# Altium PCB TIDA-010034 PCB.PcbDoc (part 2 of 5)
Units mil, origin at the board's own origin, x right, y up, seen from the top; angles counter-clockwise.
Board outline 4497.63 x 4881.81 mil, 4 copper layers (Top Layer, Signal Layer 1, Signal Layer 2, Bottom Layer), stack 62.18 mil thick; 483 components, 240 nets, 1255 pads, 589 vias.
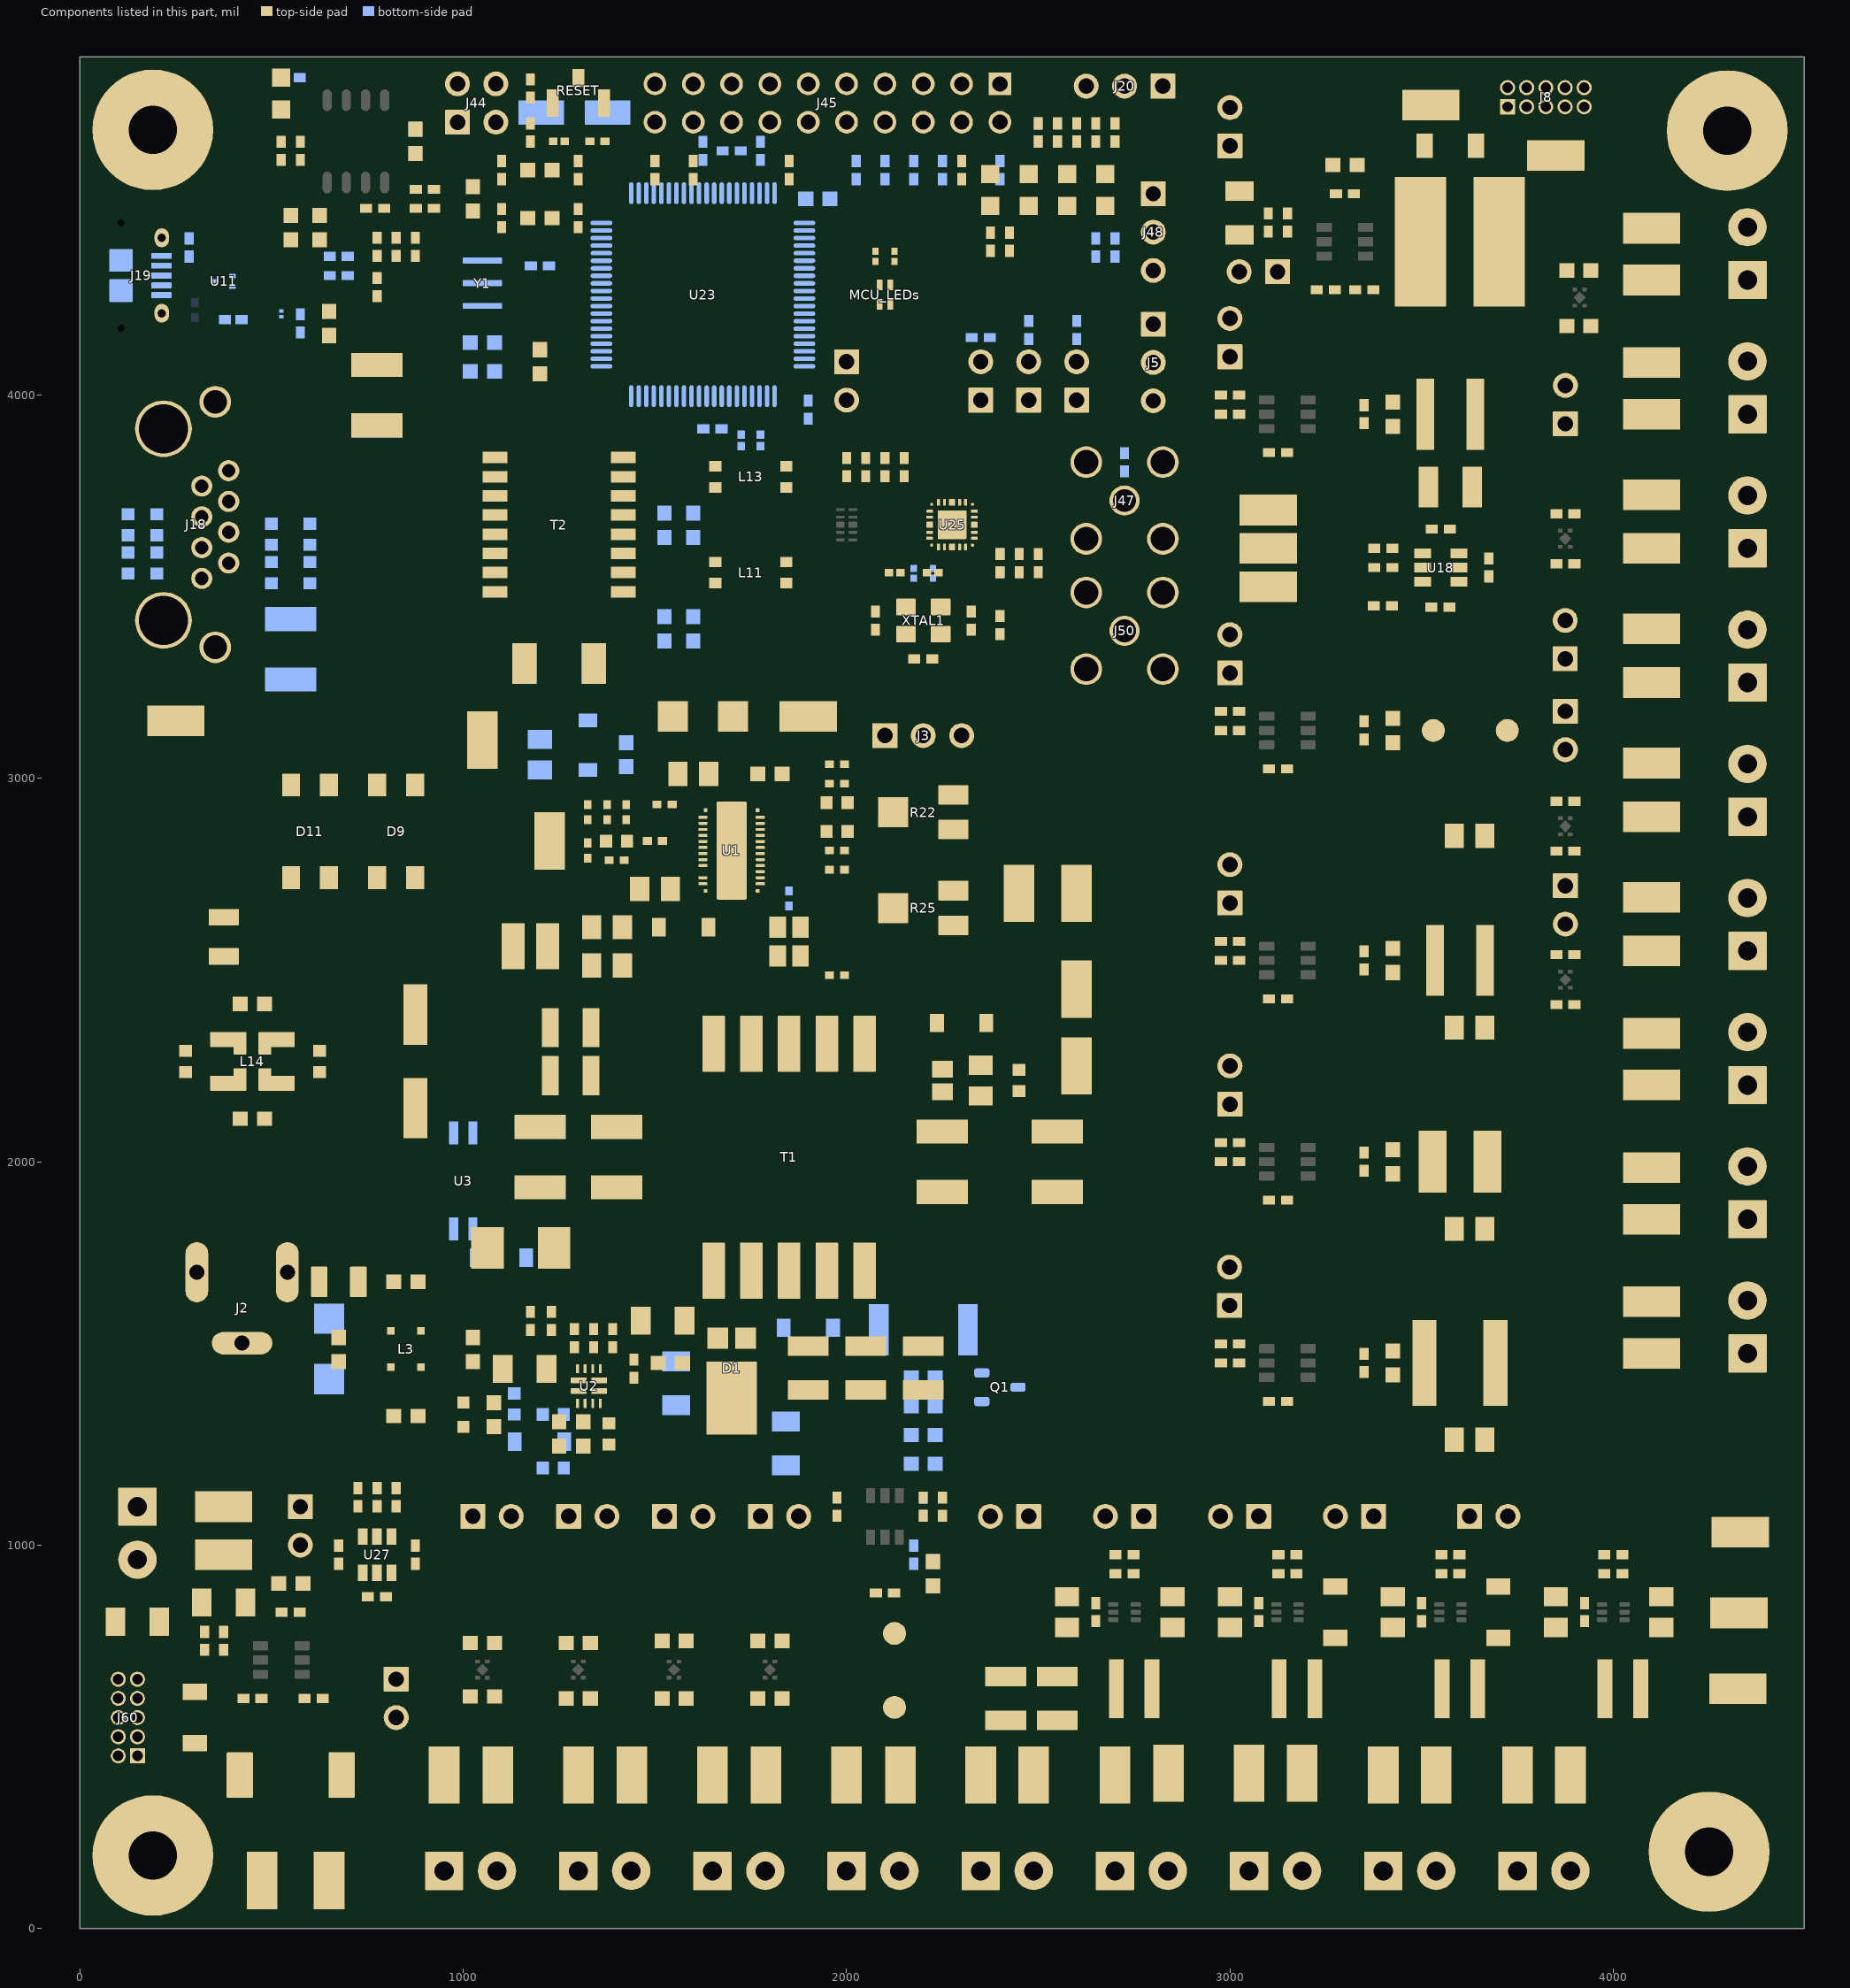
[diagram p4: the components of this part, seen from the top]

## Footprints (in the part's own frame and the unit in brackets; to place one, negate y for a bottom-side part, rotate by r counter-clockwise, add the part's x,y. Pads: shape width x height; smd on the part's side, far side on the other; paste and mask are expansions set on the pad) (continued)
DRT0003A [mm] "SOTFL, 3-Leads, Body 1x1mm (inc leads), Pitch 0.35mm"
  rect 0.3x0.45 smd: 1(-0.35,-0.575) 2(0.35,-0.575) 3(0,0.575)
  silkscreen extent -0.85,-0.63 0.67,0.58, body extent -0.52,-0.42 0.52,0.42, height 0.5
ECS_ECS-33Q [mm] "SMD, 4-Leads, Body 2.5x3.2mm"
  rrect9% 1.1x1.3 smd: 1(-0.9,1.15) 2(-0.9,-1.15) 3(0.9,-1.15) 4(0.9,1.15)
  silkscreen extent -1.75,0.6 -1.75,1.7, body extent -1.3,-1.65 1.3,1.65, height 0.81
FCC_disclaimer [mil]
FCI_10118194-0001LF [mm] "USB-micro B USB 2.0, 0.65mm, 5 Pos, R/A, SMT"
  rrect25% 0.4x1.35 smd: 1(-1.3,4.125) 2(-0.65,4.125) 3(0,4.125) 4(0.65,4.125) 5(1.3,4.125)
  rrect100% 1.25x0.95 hole 0.55 slot 0.85 at 0 deg: 6(-2.5,4.15) 7(2.5,4.15)
  round 0 hole 0.5 slot 1.15 at 90 deg: 8(-3.5,1.45) 9(3.5,1.45)
  rrect7% 1.5x1.55 smd: 10(-1,1.45) 11(1,1.45)
  Top Layer region: -3.445,0.675 -3.636,0.713 -3.799,0.821 -3.907,0.984 -3.945,1.175 -3.945,1.175 -3.945,1.175 -3.945,1.725 -3.907,1.916 -3.799,2.079 -3.636,2.187 -3.445,2.225 -3.445,2.225 -2.3,2.225 -2.3,0.675
  Top Layer region: 3.445,0.675 3.636,0.713 3.799,0.821 3.907,0.984 3.945,1.175 3.945,1.175 3.945,1.175 3.945,1.725 3.907,1.916 3.799,2.079 3.636,2.187 3.445,2.225 3.445,2.225 2.3,2.225 2.3,0.675
  silkscreen extent -4,2.6 3.7,4.3, body extent -4.02,-1.23 4.03,4.35, height 2.73
Fuse_USF1206 [mm] "SMD, 2-Leads, Body 3.2x1.6mm"
  rrect9% 1.1x2 smd: 1(-1.3,0) 2(1.3,0)
  body extent -1.6,-0.8 1.6,0.8, height 0.65
HSMF-C165_RG [mm] "SMD, 4-Leads, Body 1.6x0.8mm"
  rect 0.7x0.4 smd: 1(-0.65,0.35) 2(-0.65,-0.35) 3(0.65,0.35) 4(0.65,-0.35)
  silkscreen extent -1,-0.8 1.5,0.8, body extent -0.85,-0.45 0.85,0.45, height 0.51
IND_1255AY [mm] "Toko DG6045C 1255AY"
  rect 1.6x5.7 smd: 1(-2.35,0) 2(2.35,0)
  silkscreen extent -1.25,-2.8 1.25,2.8, body extent -3.15,-3.15 3.15,3.15, height 4.5
Keystone_1902C [mil] "Hex Standoff, 4-40 threaded, nylon"
  body extent -145,-126 146,126, height 501
Keystone_5019 [mm] "Test Point, Miniature, SMT"
  rect 3.8x2.03 smd: 1(0,0)
  silkscreen extent -2.31,-1.42 2.31,1.42, body extent -1.9,-1.02 1.9,1.02, height 2.29
Linkcom_LDT0937-50 [mm] "SMD, 10-Leads, Body 14x15.1mm, Pitch 2.5mm"
  rrect7% 1.5x3.725 smd paste+0: 1(-5,7.512) 2(-2.5,7.512) 3(0,7.512) 4(2.5,7.512) 5(5,7.512) 6(5,-7.512) 7(2.5,-7.512) 8(0,-7.512) 9(-2.5,-7.512) 10(-5,-7.512)
  silkscreen extent -7.4,-7.55 7,7.55, body extent -7,-8.75 7,8.75, height 14
LPS8045B [mm] "COILCRAFT"
  rect 3.4x8.61 smd: 1(-2.605,0) 2(2.605,0)
  silkscreen extent -0.6,-4.15 0.6,4.15, body extent -4.04,-4.04 4.04,4.04, height 4.7
LQH5BPN_38 [mm] "MURATA"
  rect 1.85x4.1 smd: 1(-1.825,0) 2(1.825,0)
  silkscreen extent -2.5,-2.65 2.5,2.65, body extent -2.55,-2.55 2.55,2.55, height 4
ME3220 [mm] "Coilcraft SMT Power Inductor ME3220 inductors"
  rect 1.52x3.05 smd: 1(-1.145,0) 2(1.145,0)
  silkscreen extent -2.38,-1.88 2.34,1.88, body extent -1.75,-1.41 1.75,1.4
MF06A_N [mm] "SOT23, 6-Leads, Body 2.9x1.6mm, Pitch 0.95mm, Lead Span 2.8mm, IPC Medium Density"
  rect 1.1x0.65 smd: 1(-1.2,0.95) 2(-1.2,0) 3(-1.2,-0.95) 4(1.2,-0.95) 5(1.2,0) 6(1.2,0.95)
  silkscreen extent -1.33,-1.55 0.25,1.95, body extent -0.9,-1.55 0.9,1.55, height 1.22
MFP04A [mm] "FAIRCHILD optocoupler"
  rect 1.52x0.61 smd: 1(-3.175,0.635) 2(-3.175,-0.635) 3(3.175,-0.635) 4(3.175,0.635)
  silkscreen extent -2.28,-1.4 2.2,1.8, body extent -3.6,-1.34 3.6,1.34, height 2.39
MiniDIP [mm] "Land pattern created based on STEP model."
  rect 1.52x1.2 smd: 1(-3.075,1.25) 2(-3.075,-1.25) 3(3.075,-1.25) 4(3.075,1.25)
  silkscreen extent -4.19,-2.54 4.19,2.54, body extent -3.5,-2.45 3.5,2.45, height 2.75
Murata_CSTCR_G15L [mm] "Murata"
  rrect25% 0.4x2.6 smd: 1(-1.5,0) 2(0,0) 3(1.5,0)
  body extent -2.3,-1.05 2.3,1.05, height 1.2
MuRata_DLW44SN [mm] "SMD, 4-Leads, Body 4.2x4.2mm"
  rrect12% 1.5x0.85 smd: 1(-1.2,0.825) 2(-1.2,-0.825) 3(1.2,-0.825) 4(1.2,0.825)
  rrect10% 1x2.4 smd: ""(-1.45,1.6) ""(-1.45,-1.6) ""(1.45,1.6) ""(1.45,-1.6)
  silkscreen extent -0.7,-2.2 0.6,2.5, body extent -2.1,-2.1 2.1,2.1, height 1.5
"NY PMS 440 0025 PH" [mm] "4-40 nylon screw and mounting hole"
  round 8 hole 3.2: 1(0,0)
  body extent -3.3,-3.3 3.3,3.3, height 2.69
Pb-Free_Overlay_Small [mil]
  silkscreen extent -46,-46 46,46
PN0080A_N [mm] "QFP, 80-Leads, Body 12x12mm, Pitch 0.5mm, IPC Medium Density"
  oval 1.45x0.3 smd: 1(-6.725,4.75) 2(-6.725,4.25) 3(-6.725,3.75) 4(-6.725,3.25) 5(-6.725,2.75) 6(-6.725,2.25) 7(-6.725,1.75) 8(-6.725,1.25) 9(-6.725,0.75) 10(-6.725,0.25) 11(-6.725,-0.25) 12(-6.725,-0.75) 13(-6.725,-1.25) 14(-6.725,-1.75) 15(-6.725,-2.25) 16(-6.725,-2.75) 17(-6.725,-3.25) 18(-6.725,-3.75) 19(-6.725,-4.25) 20(-6.725,-4.75) 41(6.725,-4.75) 42(6.725,-4.25) 43(6.725,-3.75) 44(6.725,-3.25) 45(6.725,-2.75) 46(6.725,-2.25) 47(6.725,-1.75) 48(6.725,-1.25) 49(6.725,-0.75) 50(6.725,-0.25) 51(6.725,0.25) 52(6.725,0.75) 53(6.725,1.25) 54(6.725,1.75) 55(6.725,2.25) 56(6.725,2.75) 57(6.725,3.25) 58(6.725,3.75) 59(6.725,4.25) 60(6.725,4.75)
  oval 0.3x1.45 smd: 21(-4.75,-6.725) 22(-4.25,-6.725) 23(-3.75,-6.725) 24(-3.25,-6.725) 25(-2.75,-6.725) 26(-2.25,-6.725) 27(-1.75,-6.725) 28(-1.25,-6.725) 29(-0.75,-6.725) 30(-0.25,-6.725) 31(0.25,-6.725) 32(0.75,-6.725) 33(1.25,-6.725) 34(1.75,-6.725) 35(2.25,-6.725) 36(2.75,-6.725) 37(3.25,-6.725) 38(3.75,-6.725) 39(4.25,-6.725) 40(4.75,-6.725) 61(4.75,6.725) 62(4.25,6.725) 63(3.75,6.725) 64(3.25,6.725) 65(2.75,6.725) 66(2.25,6.725) 67(1.75,6.725) 68(1.25,6.725) 69(0.75,6.725) 70(0.25,6.725) 71(-0.25,6.725) 72(-0.75,6.725) 73(-1.25,6.725) 74(-1.75,6.725) 75(-2.25,6.725) 76(-2.75,6.725) 77(-3.25,6.725) 78(-3.75,6.725) 79(-4.25,6.725) 80(-4.75,6.725)
  silkscreen extent -6.85,-5.6 5.6,5.6, body extent -7,-7 7,7, height 1.56
PowerDI5 [mm] "Diodes Inc recommended land pattern, ap02001.pdf rev 60"
  rect 1.4x1.39 smd: 1(-1.991,0.92) 2(-1.991,-0.92)
  rect 4.86x3.36 smd: 3(1.991,0)
  silkscreen extent -1.7,-2.1 3.8,2.1, body extent -2.27,-2.03 4.33,2.03, height 1.17
PULSE_H2019FNL [mil] "PULSE"
  rect 65x30 smd paste+0: 1(-167.51,174.99) 2(-167.51,124.99) 3(-167.51,74.99) 4(-167.51,24.99) 5(-167.51,-25.01) 6(-167.51,-75.01) 7(-167.51,-125.01) 8(-167.51,-175.01) 9(167.49,-175.01) 10(167.49,-125.01) 11(167.49,-75.01) 12(167.49,-25.01) 13(167.49,24.99) 14(167.49,74.99) 15(167.49,124.99) 16(167.49,174.99)
  silkscreen extent -208,-250 179,250, body extent -179,-250 179,250, height 236
QTLP630C_Green [mm] "SMT, 2-Leads, Body 2x1.25mm"
  rect 1.2x1.2 smd: 1(-1.05,0) 2(1.05,0)
  silkscreen extent -0.15,-0.8 2.15,0.8, body extent -1.1,-0.73 1.1,0.73, height 1.22
RJJ0023B [mm] "SMD, 23-Leads, Body 4x6mm"
  rrect50% 0.6x0.2 smd: 1(-1.9,2.2) 2(-1.9,1.8) 3(-1.9,1.4) 4(-1.9,1) 5(-1.9,0.6) 6(-1.9,0.2) 7(-1.9,-0.2) 8(-1.9,-0.6) 9(-1.9,-1) 10(-1.9,-1.4) 11(-1.9,-1.8) 12(-1.9,-2.2) 13(1.9,-2.2) 14(1.9,-1.8) 15(1.9,-1.4) 16(1.9,-1) 17(1.9,-0.6) 18(1.9,-0.2) 19(1.9,0.2) 20(1.9,0.6) 21(1.9,1) 23(1.9,1.8) 24(1.9,2.2)
  rrect10% 2x6.5 smd paste-2 mask-2: 25(0,0)
  rrect40% 0.25x0.25 smd: A1(-1.725,2.675) A2(-1.725,-2.675) A3(1.725,-2.675) A4(1.725,2.675)
  rrect50% 0.2x0.46 on Top Paste: ""(-0.8,2.97) ""(-0.8,-2.97) ""(-0.4,2.97) ""(-0.4,-2.97) ""(0,2.97) ""(0,-2.97) ""(0.4,2.97) ""(0.4,-2.97) ""(0.8,2.97) ""(0.8,-2.97)
  rrect12% 0.85x1.12 on Top Paste: ""(-0.525,1.98) ""(-0.525,0.66) ""(-0.525,-0.66) ""(-0.525,-1.98) ""(0.525,1.98) ""(0.525,0.66) ""(0.525,-0.66) ""(0.525,-1.98)
  silkscreen extent -2.2,-3.2 2.2,3.2, body extent -2,-3 2,3, height 1
RLL0024A [mm] "QFN, 24-Leads, Body 3x3mm"
  rrect50% 0.45x0.2 smd: 1(-1.475,0.9) 2(-1.475,0.5) 4(-1.475,-0.5) 5(-1.475,-0.9) 13(1.475,-0.9) 14(1.475,-0.5) 16(1.475,0.5) 17(1.475,0.9)
  rrect25% 0.45x0.4 smd: 3(-1.475,0) 15(1.475,0)
  rrect50% 0.2x0.2 smd: 6(-1.35,-1.35) 12(1.35,-1.35) 18(1.35,1.35) 24(-1.35,1.35)
  rrect50% 0.2x0.45 smd: 7(-0.9,-1.475) 8(-0.5,-1.475) 10(0.5,-1.475) 11(0.9,-1.475) 19(0.9,1.475) 20(0.5,1.475) 22(-0.5,1.475) 23(-0.9,1.475)
  rrect25% 0.4x0.45 smd: 9(0,-1.475) 21(0,1.475)
  rrect5% 1.9x1.9 smd paste-1.9: 25(0,0)
  rrect6% 1.71x1.71 on Top Paste: ""(0,0)
  silkscreen extent -1.78,-1.78 1.78,1.78, body extent -1.58,-1.58 1.58,1.58, height 1.01
RUX0012A [mm] "VQFN-HR-12"
  rrect25% 1.05x0.4 smd: 1(-0.675,0.325) 2(-0.675,-0.375) 7(0.675,-0.375) 8(0.675,0.325)
  rrect40% 0.2x0.6 smd: 3(-0.75,-1.15) 4(-0.25,-1.15) 5(0.25,-1.15) 6(0.75,-1.15) 9(0.75,1.15) 10(0.25,1.15) 11(-0.25,1.15) 12(-0.75,1.15)
  silkscreen extent -1.15,-1.4 1.15,1.35, body extent -1.05,-1.3 1.05,1.3, height 1
Samtec_HTSW-102-07-G-S [mm] "Samtec 100mil, 1x2, 230 mil above insulator"
  rrect6% 1.65x1.65 hole 1.016: 1(-1.27,0)
  round 1.65 hole 1.016: 2(1.27,0)
  silkscreen extent -3.3,-1.27 2.54,1.27, body extent -2.54,-1.27 2.54,1.27, height 8.38
Samtec_HTSW-103-07-G-S [mm] "Samtec 100mil, 1x3, 230 mil above insulator"
  rrect6% 1.65x1.65 hole 1.016: 1(-2.54,0)
  round 1.65 hole 1.016: 2(0,0) 3(2.54,0)
  silkscreen extent -4.57,-1.27 3.81,1.27, body extent -3.81,-1.27 3.81,1.27, height 8.38
SM_RADIAL_E [mm] "8 x 6.2mm:  Panasonic E"
  rect 4x1.6 smd: 1(-3.1,0) 2(3.1,0)
  silkscreen extent -4.25,-4.25 4.25,4.25, body extent -4.25,-4.25 4.25,4.25, height 6.5
SMA [mm] "Molded Diode, 2-Leads, Body 4.3x2.6mm, IPC Medium Density, based on OnSemi component dimensions and land pattern"
  rect 2x2 smd: 1(-2,0) 2(2,0)
  silkscreen extent -3.66,-1.57 2.79,1.57, body extent -2.6,-1.3 2.6,1.3, height 2.42
SMB [mil] "Molded Diode, 2-Leads, Body 5.4x3.6mm, IPC Medium Density, based on OnSemi component dimensions"
  rect 85x107.99 smd: 1(-87.01,0) 2(87.01,0)
  silkscreen extent -155,-82 125,82, body extent -106,-71 106,71, height 91
SOD-123 [mm] "On Semi recommended land pattern"
  rect 0.915x1.22 smd: 1(-1.637,0) 2(1.637,0)
  silkscreen extent -2.74,-1.17 2.03,1.17, body extent -1.93,-0.9 1.93,0.9, height 1.35
SOD-523 [mm] "NXP Semiconductor recommended land pattern, nominal STEP model"
  rect 0.8x0.6 smd paste-0.05: 1(-0.55,0) 2(0.55,0)
  silkscreen extent -1.65,-0.66 1.2,0.66, body extent -0.8,-0.4 0.8,0.4, height 0.72
SOT-23 [mm] "SOT23, 3-Leads, Body 2.9x1.3mm, Pitch 0.95mm, Lead Span 2.5mm, IPC Medium Density"
  rrect50% 1x0.6 smd: 1(-1.2,0.95) 2(-1.2,-0.95) 3(1.2,0)
  silkscreen extent -1.63,-1.5 0.7,1.5, body extent -1.16,-1.45 1.21,1.45, height 1
SRT8045 [mil] "SMD, 2-Leads, Body 8x8.4mm"
  round 60 smd: 1(-94.49,0) 2(98.43,0)
  Top Layer region: 157.48,-102.36 102.36,-157.48 35.43,-157.48 35.43,157.48 157.48,157.48
  Top Layer region: -157.48,-102.36 -102.36,-157.48 -35.43,-157.48 -35.43,157.48 -157.48,157.48
  silkscreen extent -169,-177 169,177, body extent -163,-171 163,171, height 181
Sullins_xxxC010DAAN [mm] "Header, 2.54mm, 10x2, TH"
  rect 1.5x1.5 hole 1: 1(-1.27,11.43)
  round 1.5 hole 1: 2(1.27,11.43) 3(-1.27,8.89) 4(1.27,8.89) 5(-1.27,6.35) 6(1.27,6.35) 7(-1.27,3.81) 8(1.27,3.81) 9(-1.27,1.27) 10(1.27,1.27) 11(-1.27,-1.27) 12(1.27,-1.27) 13(-1.27,-3.81) 14(1.27,-3.81) 15(-1.27,-6.35) 16(1.27,-6.35) 17(-1.27,-8.89) 18(1.27,-8.89) 19(-1.27,-11.43) 20(1.27,-11.43)
  silkscreen extent -2.5,-12.7 2.5,13.14, body extent -2.5,-12.7 2.5,12.7, height 8.34
SW_B3U-1100P [mm] "SMD, 3-Leads, Body 3x2.5mm"
  rect 0.8x1.8 smd: 1(-1.7,0) 2(1.7,0)
  rect 0.8x1.2 smd: 3(0,1.65)
  silkscreen extent -1.83,-1.25 1.5,1.77, body extent -2,-1.25 2,1.9, height 1.6
TDK_ACT45L [mm] "SMD, 4-Leads, Body 4.5x3.2mm"
  rect 0.8x0.7 smd: 1(-2.35,0.7) 2(-2.35,-0.7) 3(2.35,-0.7) 4(2.35,0.7)
  silkscreen extent -2.35,-1.7 2.25,2, body extent -2.25,-1.7 2.25,1.7, height 2.95
TE_5-1814832-1 [mm] "SMA Straight PCB Socket Die Cast, TH"
  round 2 hole 1.5: 1(0,0)
  round 2.1 hole 1.6: 2(-2.54,2.54) 3(-2.54,-2.54) 4(2.54,-2.54) 5(2.54,2.54)
  silkscreen extent -3.2,-3.2 3.2,3.2, body extent -3.2,-3.2 3.2,3.2, height 9.5
TEC_1-406541-1 [mm] "TE Connectivity"
  round 1.4 hole 0.89: 1(3.56,-0.18) 2(2.54,1.6) 3(1.52,-0.18) 4(0.5,1.6) 5(-0.52,-0.18) 6(-1.54,1.6) 7(-2.56,-0.18) 8(-3.58,1.6)
  round 2.1 hole 1.57: 9(8.12,0.71) 10(-8.14,0.71)
  round 3.759 hole 3.251: 11(6.34,-2.72) 12(-6.36,-2.72)
  silkscreen extent -9.69,-8 9.69,8.06, body extent -9.33,-8 9.31,7.75, height 14.8
TERM_BLK_ED555-2DS [mil]
  rrect4% 100x100 hole 50: 1(0,0)
  round 100 hole 50: 2(138,0)
  silkscreen extent -96,-159 215,113, body extent -69,-150 207,106, height 323
TSW-102-07-G-D [mm] "Samtec 100mil, 2x2, 230 mil above insulator"
  rrect6% 1.65x1.65 hole 1.016: 1(-1.27,-1.27)
  round 1.65 hole 1.016: 2(-1.27,1.27) 3(1.27,-1.27) 4(1.27,1.27)
  silkscreen extent -2.77,-3.09 2.54,2.54, body extent -2.54,-2.54 2.54,2.54, height 8.38
TSW-102-07-G-S [mm] "Samtec 100mil, 1x2, 230 mil above insulator"
  rrect6% 1.65x1.65 hole 1.016: 1(-1.27,0)
  round 1.65 hole 1.016: 2(1.27,0)
  silkscreen extent -2.54,-1.27 2.54,1.65, body extent -2.54,-1.27 2.54,1.27, height 8.38
TSW-103-07-X-S [mm] "Samtec Header, 100mil, 1x3"
  rect 1.65x1.65 hole 1.016: 1(-2.54,0)
  round 1.65 hole 1.016: 2(0,0) 3(2.54,0)
  silkscreen extent -4.57,-1.52 4.06,1.52, body extent -3.81,-1.27 3.81,1.27, height 8.38
WL-SMCW_YELLOW [mm] "WURTH"
  rect 0.8x0.8 smd: 1(-0.8,0) 2(0.8,0)
  silkscreen extent -1.9,-0.8 1.2,0.8, body extent -0.85,-0.45 0.85,0.45, height 0.8
X3-DFN0603-2 [mm] "SMD, 2-Leads, Body 0.62x0.32mm"
  rect 0.23x0.3 smd mask+0.102: 1(-0.19,0) 2(0.19,0)
  silkscreen extent -0.69,-0.48 0.32,0.48, body extent -0.32,-0.17 0.32,0.17, height 0.35
XEL4030_310 [mm] "SMD, 2-Leads, Body 4x4mm, Pitch 2.37mm"
  rect 0.98x3.9 smd: 1(-1.185,0) 2(1.185,0)
  silkscreen extent -2.3,-2.3 2.3,2.3, body extent -2.15,-2.15 2.15,2.15, height 3.1
XFL5030 [mm] "SMD, 2-Leads, Body 5.48x5.28mm"
  rect 1.18x4.7 smd: 1(-1.655,0) 2(1.655,0)
  silkscreen extent -2.74,-2.84 2.74,2.84, body extent -2.74,-2.84 2.74,2.84, height 3.1

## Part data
1.1V 1.1V 1.5VA 1.5VA 1.8VA 1.8VA 1.8VD 1.8VD 1.35V 1.35V 2.8VA 2.8VA 3.3V 3.3VA 3.3VA 3.3VD 5V 5V 12V EARTH GND GND GND GND GND GND GND GND GND GND GND GND GND GND GND GND GND GND GND Loop PGND RSNS SEQ1_FLAG1 SEQ1_FLAG2 SEQ1_FLAG3 SEQ2_FLAG1 SEQ2_FLAG2 SEQ2_FLAG3 VBIAS VCC VLED1 VLED1_FB VLED2 VLED2_FB VPD VSS: library part 5019, "Test Point, Miniature, SMT", Manufacturer=Keystone, Supplier Part Number 1=36-5019TR-ND
+3.3V LED0_H LED0_L LED2_H LED2_L: library part CMP-0002917-1, "LED, Green, SMD", Color=Green, Manufacturer=Everlight, Supplier Part Number 1=1080-1411-1-ND, Value1=W, Value2=2.1V
+12V_PoE: "LED, Yellow, SMD", Color=yellow, Manufacturer="Wurth Elektronik", Supplier Part Number 1=732-4981-1-ND, Value1=W, Value2=2V
C1 C2 C27 C28: "CAP, CERM, 2200 pF, 2000 V, +/- 10%, X7R, 1812", Cap_Case=1812, Manufacturer=TDK, Supplier Part Number 1=445-2389-1-ND, TempCo=X7R, Tolerance_%=10, Value1=Unknown, Value2=2000V, ValueDisplayed=2200pF
C3 C14: "CAP, CERM, 0.1 µF, 100 V, +/- 10%, X7R, 0805", Cap_Case=0805, Manufacturer=TDK, Supplier Part Number 1=445-1418-1-ND, TempCo=X7R, Tolerance_%=10, Value1="0.020726 ohm", Value2=100V, ValueDisplayed=0.1µF
C4: "CAP, AL, 10 µF, 100 V, +/- 20%, AEC-Q200 Grade 3, SMD", Cap_Case=8.0x6.0mm, Manufacturer=Panasonic, Supplier Part Number 1=PCE3966CT-ND, Tolerance_%=20, Value1=Unknown, Value2=100V, ValueDisplayed=10µF
C5 C6: "CAP, CERM, 2.2 µF, 100 V, +/- 10%, X7R, 1210", Cap_Case=1210, Manufacturer=MuRata, Supplier Part Number 1=490-3385-1-ND, TempCo=X7R, Tolerance_%=10, Value1="0.007 ohm", Value2=100V, ValueDisplayed=2.2µF
C7 C8 C9: "CAP, CERM, 22 µF, 25 V,+/- 10%, X7R, 1210", Cap_Case=1210, Manufacturer=MuRata, Supplier Part Number 1=490-5313-1-ND, TempCo=X7R, Tolerance_%=10, Value1="0.002334 ohm", Value2=25V, ValueDisplayed=22µF
C10: "CAP, CERM, 680 pF, 100 V, +/- 10%, X7R, 0603", Cap_Case=0603, Manufacturer=AVX, Supplier Part Number 1=478-1198-1-ND, TempCo=X7R, Tolerance_%=10, Value1="0.332 ohm", Value2=100V, ValueDisplayed=680pF
C11 C16: "CAP, CERM, 1 µF, 50 V,+/- 10%, X7R, 0805", Cap_Case=0805, Manufacturer=MuRata, Supplier Part Number 1=490-4736-1-ND, TempCo=X7R, Tolerance_%=10, Value2=50V, ValueDisplayed=1µF
C12 C15 C26: "CAP, CERM, 0.1 µF, 50 V,+/- 10%, X7R, 0603", Cap_Case=0603, Manufacturer=AVX, Supplier Part Number 1=478-5052-1-ND, TempCo=X7R, Tolerance_%=10, Value2=50V, ValueDisplayed=0.1µF
C13: "CAP, CERM, 0.22 µF, 100 V,+/- 10%, X7R, 0805", Cap_Case=0805, Manufacturer=MuRata, Supplier Part Number 1=GRM21AR72A224KAC5-ND, TempCo=X7R, Tolerance_%=10, Value2=100V, ValueDisplayed=0.22µF
C17: "CAP, CERM, 100 pF, 50 V,+/- 5%, C0G/NP0, 0402", Cap_Case=0402, Manufacturer="Wurth Elektronik", Supplier Part Number 1=732-7475-1-ND, TempCo=C0G/NP0, Tolerance_%=5, Value2=50V, ValueDisplayed=100pF
C18: "CAP, CERM, 0.01 µF, 100 V,+/- 20%, X7R, 0603", Cap_Case=0603, Manufacturer=AVX, Supplier Part Number 1=478-3701-1-ND, TempCo=X7R, Tolerance_%=20, Value1="0.098 ohm", Value2=100V, ValueDisplayed=0.01µF
C19 C20 C54 C55: "CAP, CERM, 1000 pF, 100 V, +/- 10%, X7R, 0603", Cap_Case=0603, Manufacturer=MuRata, Supplier Part Number 1=490-1472-1-ND, TempCo=X7R, Tolerance_%=10, Value1=Unknown, Value2=100V, ValueDisplayed=1000pF
C22 C25: "CAP, CERM, 0.1 µF, 25 V, +/- 10%, X7R, 0603", Cap_Case=0603, Manufacturer=TDK, Supplier Part Number 1=445-1316-1-ND, TempCo=X7R, Tolerance_%=10, Value1=Unknown, Value2=25V, ValueDisplayed=0.1µF
C24: "CAP, CERM, 2200 pF, 50 V, +/- 10%, X7R, 0603", Cap_Case=0603, Manufacturer=MuRata, Supplier Part Number 1=490-1500-1-ND, TempCo=X7R, Tolerance_%=10, Value1=Unknown, Value2=50V, ValueDisplayed=2200pF
C29 C30 C38 C39 C46 C50 C76 C137: "CAP, CERM, 0.1 µF, 10 V,+/- 10%, X7R, 0402", Cap_Case=0402, Manufacturer=MuRata, Supplier Part Number 1=GRM155R71A104KA01D-ND, TempCo=X7R, Tolerance_%=10, Value2=10V, ValueDisplayed=0.1µF
C31 C40 C47 C51: "CAP, CERM, 47 µF, 10 V,+/- 20%, X5R, 0805", Cap_Case=0805, Manufacturer=TDK, Supplier Part Number 1=445-8239-1-ND, TempCo=X5R, Tolerance_%=20, Value1="0.00294 ohm", Value2=10V, ValueDisplayed=47µF
C32 C138: "CAP, CERM, 33 µF, 25 V,+/- 20%, X5R, 1206", Cap_Case=1206, Manufacturer=TDK, Supplier Part Number 1=445-8046-1-ND, TempCo=X5R, Tolerance_%=20, Value1="0.002648 ohm", Value2=25V, ValueDisplayed=33µF
C33 C35 C41 C44 C48 C52 C65 C68 C71 C83 C84 C139: "CAP, CERM, 10 µF, 25 V,+/- 20%, X5R, 0603", Cap_Case=0603, Manufacturer=MuRata, Supplier Part Number 1=490-7202-1-ND, TempCo=X5R, Tolerance_%=20, Value2=25V, ValueDisplayed=10µF
C34 C36 C42 C45 C49 C53 C80 C85 C88 C91 C94 C95 C128 C140: "CAP, CERM, 0.1 µF, 25 V,+/- 10%, X7R, 0402", Cap_Case=0402, Manufacturer=MuRata, Supplier Part Number 1=490-10698-1-ND, TempCo=X7R, Tolerance_%=10, Value2=25V, ValueDisplayed=0.1µF
C37 C141: "CAP, CERM, 0.082 µF, 10 V,+/- 10%, X7R, 0402", Cap_Case=0402, Manufacturer=MuRata, Supplier Part Number 1=GRM155R71A823KA01D-ND, TempCo=X7R, Tolerance_%=10, Value2=10V, ValueDisplayed=0.082µF
C43 C81 C82: "CAP, CERM, 47 µF, 16 V,+/- 20%, X5R, 1210", Cap_Case=1210, Manufacturer=MuRata, Supplier Part Number 1=81-GRM32ER61C476ME15, TempCo=X5R, Tolerance_%=20, Value1="0.002 ohm", Value2=16V, ValueDisplayed=47µF
C56 C74 C75 C142: "CAP, CERM, 1000 pF, 100 V,+/- 10%, X7R, 0603", Cap_Case=0603, Manufacturer=MuRata, Supplier Part Number 1=490-1472-1-ND, TempCo=X7R, Tolerance_%=10, Value2=100V, ValueDisplayed=1000pF
C57: "CAP, CERM, 1000 pF, 2000 V, +/- 10%, X7R, 1812", Cap_Case=1812, Manufacturer=MuRata, TempCo=X7R, Tolerance_%=10, Value1=Unknown, Value2=2000V, ValueDisplayed=1000pF
C58 C59 C60 C61: "CAP, CERM, 0.01 µF, 100 V, +/- 10%, X7R, 0603", Cap_Case=0603, Manufacturer=MuRata, Supplier Part Number 1=GRM188R72A103KA01D-ND, TempCo=X7R, Tolerance_%=10, Value1=Unknown, Value2=100V, ValueDisplayed=0.01µF
C62 C63 C72 C73 C119 C120 C121 C122: library part CMP-0006563-2, "CAP, CERM, 1 uF, 10 V, +/- 10%, X5R, 0402", Cap_Case=0402, Manufacturer=MuRata, Supplier Part Number 1=490-3890-1-ND, TempCo=X5R, Tolerance_%=10%, Value1=Unknown, Value2=10V, ValueDisplayed=1uF
C64: "CAP, CERM, 1 µF, 16 V,+/- 10%, X7R, 0603", Cap_Case=0603, Manufacturer=MuRata, Supplier Part Number 1=490-10734-1-ND, TempCo=X7R, Tolerance_%=10, Value2=16V, ValueDisplayed=1µF
C66 C67: "CAP, CERM, 2.2 µF, 16 V,+/- 10%, X7R, 0603", Cap_Case=0603, Manufacturer=MuRata, Supplier Part Number 1=81-GRM188Z71C225KE3D, TempCo=X7R, Tolerance_%=10, Value2=16V, ValueDisplayed=2.2µF
C69: library part CMP-0006389-2, "CAP, CERM, 470 pF, 25 V, +/- 5%, C0G/NP0, 0402", Cap_Case=0402, Manufacturer=MuRata, Supplier Part Number 1=GRM1555C1E471JA01D-ND, TempCo=C0G/NP0, Tolerance_%=5%, Value1=Unknown, Value2=25V, ValueDisplayed=470pF
C70: "CAP, CERM, 0.1 µF, 16 V,+/- 10%, X7R, 0402", Cap_Case=0402, Manufacturer=MuRata, Supplier Part Number 1=490-4759-2-ND, TempCo=X7R, Tolerance_%=10, Value2=16V, ValueDisplayed=0.1µF
C77 C92: "CAP, CERM, 10 µF, 10 V,+/- 20%, X7R, 0805", Cap_Case=0805, Manufacturer=MuRata, Supplier Part Number 1=490-8316-1-ND, TempCo=X7R, Tolerance_%=20, Value2=10V, ValueDisplayed=10µF
C78: "CAP, CERM, 75 pF, 50 V,+/- 5%, C0G/NP0, 0402", Cap_Case=0402, Manufacturer=MuRata, Supplier Part Number 1=81-GRM1555C1H750JA1D, TempCo=C0G/NP0, Tolerance_%=5, Value2=50V, ValueDisplayed=75pF
C79 C87 C90 C93: "CAP, CERM, 4.7 µF, 16 V,+/- 10%, X7R, 0805", Cap_Case=0805, Manufacturer=MuRata, Supplier Part Number 1=490-4522-1-ND, TempCo=X7R, Tolerance_%=10, Value1="0.006 ohm", Value2=16V, ValueDisplayed=4.7µF
C86 C89: "CAP, CERM, 22 µF, 16 V,+/- 20%, X5R, 1206", Cap_Case=1206, Manufacturer=MuRata, Supplier Part Number 1=490-4739-1-ND, TempCo=X5R, Tolerance_%=20, Value1="0.006 ohm", Value2=16V, ValueDisplayed=22µF
C96 C97 C98 C100 C102 C103: "CAP, CERM, 1 µF, 10 V,+/- 10%, X5R, 0402", Cap_Case=0402, Manufacturer=MuRata, Supplier Part Number 1=490-3890-1-ND, TempCo=X5R, Tolerance_%=10, Value2=10V, ValueDisplayed=1µF
C99 C101 C129 C130 C131 C132 C133 C134 C135 C136: "CAP, CERM, 1 µF, 16 V,+/- 10%, X7R, 0603", Cap_Case=0603, Manufacturer=MuRata, Supplier Part Number 1=490-3900-1-ND, TempCo=X7R, Tolerance_%=10, Value1="0.011 ohm", Value2=16V, ValueDisplayed=1µF
C104: library part CMP-0006254-2, "CAP, CERM, 1000 pF, 50 V, +/- 5%, C0G/NP0, 0402", Cap_Case=0402, Manufacturer=TDK, Supplier Part Number 1=445-13785-1-ND, TempCo=C0G/NP0, Tolerance_%=5%, Value1=Unknown, Value2=50V, ValueDisplayed=1000pF
C105 C108: "CAP, CERM, 0.22 µF, 50 V,+/- 10%, X7R, 0603", Cap_Case=0603, Manufacturer=MuRata, Supplier Part Number 1=490-12546-1-ND, TempCo=X7R, Tolerance_%=10, Value2=50V, ValueDisplayed=0.22µF
C106: "CAP, CERM, 0.47 µF, 25 V,+/- 10%, X7R, 0603", Cap_Case=0603, Manufacturer=MuRata, Supplier Part Number 1=490-3291-1-ND, TempCo=X7R, Tolerance_%=10, Value2=25V, ValueDisplayed=0.47µF
C107: library part CMP-0007022-5, "CAP, CERM, 4.7 uF, 35 V, +/- 10%, X5R, 0603", Cap_Case=0603, Manufacturer=TDK, Supplier Part Number 1=445-9064-1-ND, TempCo=X5R, Tolerance_%=10%, Value1="0.003728 ohm", Value2=35V, ValueDisplayed=4.7uF
C109: "CAP, AL, 10 µF, 35 V, +/- 20%, 0.7 ohm, SMD", Cap_Case=E61, Manufacturer=Chemi-Con, Supplier Part Number 1=565-2555-1-ND, Tolerance_%=20, Value1="0.7 ohm", Value2=35V, ValueDisplayed=10µF
C110 C111 C112 C115 C117: library part CMP-0006641-2, "CAP, CERM, 0.1 uF, 16 V, +/- 10%, X7R, 0402", Cap_Case=0402, Manufacturer=MuRata, Supplier Part Number 1=490-3261-1-ND, TempCo=X7R, Tolerance_%=10%, Value1=Unknown, Value2=16V, ValueDisplayed=0.1uF
C113 C114: "CAP, CERM, 10 pF, 50 V,+/- 4%, C0G/NP0, 0402", Cap_Case=0402, Manufacturer=MuRata, Supplier Part Number 1=490-11374-1-ND, TempCo=C0G/NP0, Tolerance_%=4, Value2=50V, ValueDisplayed=10pF
C116 C118: library part GRM155R61A106ME11, "CAP, CERM, 10 µF, 10 V,+/- 20%, X5R, 0402", Cap_Case=0402, Manufacturer="Samsung Electro-Mechanics", Supplier Part Number 1=1276-6830-1-ND, TempCo=X5R, Tolerance_%=20, Value2=10V, ValueDisplayed=10µF
C123: library part CMP-0006674-2, "CAP, CERM, 0.01 uF, 50 V, +/- 10%, X7R, 0402", Cap_Case=0402, Manufacturer=MuRata, Supplier Part Number 1=490-4516-1-ND, TempCo=X7R, Tolerance_%=10%, Value1=Unknown, Value2=50V, ValueDisplayed=0.01uF
C124 C127: "CAP, CERM, 22 pF, 50 V,+/- 5%, C0G/NP0, 0402", Cap_Case=0402, Manufacturer=MuRata, Supplier Part Number 1=81-GRM1555C1H220JA1D, TempCo=C0G/NP0, Tolerance_%=5, Value2=50V, ValueDisplayed=22pF
C125 C126: library part CMP-0009295-2, "CAP, CERM, 4700 pF, 2000 V, +/- 10%, X7R, 1812", Cap_Case=1812, Manufacturer=AVX, Supplier Part Number 1=478-3003-1-ND, TempCo=X7R, Tolerance_%=10%, Value1=Unknown, Value2=2000V, ValueDisplayed=4700pF
D1: "Diode, Schottky, 60 V, 3 A, PowerDI5", Manufacturer="Diodes Inc.", Supplier Part Number 1=PDS360DICT-ND, Value1=3A, Value2=0.62V
D2: "Diode, Ultrafast, 200 V, 1 A, SOD-123", Manufacturer=Rohm, Supplier Part Number 1=RF071M2SCT-ND, Value1=1A, Value2=0.85V
D3 D4 D6 D7: "Diode, Switching, 100V, 0.2A, SOD-123", Manufacturer="ON Semiconductor", Supplier Part Number 1=MMSD4148T1GOSCT-ND, Value1=0.2A, Value2=1V
D5: "Diode, Schottky, 30 V, 2 A, SMB", Manufacturer="Diodes Inc.", Supplier Part Number 1=B230-FDICT-ND, Value1=2A, Value2=0.5V
D8: "Diode, Zener, 6.8 V, 500 mW, SOD-123", Manufacturer="Diodes Inc.", Power_W=0.5, Supplier Part Number 1=MMSZ5235B-FDICT-ND, Value1=0.5W
D9 D11: "Diode, Switching-Bridge, 400V, 0.8A, MiniDIP", Manufacturer="Diodes Inc.", Supplier Part Number 1=HD04DICT-ND, Value1=0.8A, Value2=1V
D10: "Diode, TVS, Uni, 58 V, 400 W, SMA", Manufacturer="Diodes Inc.", Power_W=400, Supplier Part Number 1=SMAJ58A-13-FDICT-ND, Value1=400W
D12: "Diode, Schottky, 20 V, 0.2 A, SOD-523", Manufacturer="Diodes Inc.", Supplier Part Number 1=SBR0220T5-7DICT-ND, Value1=0.2A, Value2=0.47V
D13: "Diode, TVS, Uni, 5.5 V, 11 Vc, 2-XFDFN", Manufacturer="Diodes Inc.", Power_W=0.25, Supplier Part Number 1=D5V0M1U2LP3-7DICT-ND, Value1=0.25W
D14: "Diode, TVS, Bi, 13 V, SMA", Manufacturer=Littelfuse, Power_W=3.3, Supplier Part Number 1=SMAJ13CALFDKR-ND, Value1=3.3W
F1: library part CMP-0084010-1, "Fuse, 2 A, 125VAC/VDC, SMD", Irating_A=2A, Manufacturer=Schurter, PartNumber=3413.0119.11
F2: library part CMP-0084010-1, "Fuse, 0.5 A, 125VAC/VDC, SMD", Irating_A=500mA, Manufacturer=Schurter
H1 H2 H3 H4: "Machine Screw, Round, #4-40 x 1/4, Nylon, Philips panhead", DigiKeyPartNumber=H542-ND, Manufacturer="B&F Fastener Supply"
H5 H6 H7 H8: "Standoff, Hex, 0.5\"L #4-40 Nylon", Manufacturer=Keystone, Supplier Part Number 1=36-1902C-ND
J1 J9 J12 J13 J15 J17 J24 J25 J27 J29 J31 J34 J36 J39 J40 J43 J54 J55 J57: "Terminal Block, 6A, 3.5mm Pitch, 2-Pos, TH", Manufacturer="On-Shore Technology", Supplier Part Number 1=ED1514-ND
J2: "Connector, DC Jack 2.1X5.5 mm, TH", Manufacturer="CUI Inc.", Supplier Part Number 1=CP-202AH-ND
J3: "Header, 100mil, 3x1, Gold, TH", Color=Black, Current_A=6.3, Manufacturer=Samtec, Supplier Part Number 1=SAM1029-03-ND, Voltage_V=550
J4 J6 J7 J10 J11 J14 J16 J22 J23 J26 J28 J30 J32 J33 J35 J37 J38 J41 J42 J56 J58 J59: "Header, 100mil, 2x1, Gold, TH", Color=Black, Current_A=6.3, Manufacturer=Samtec, Supplier Part Number 1=SAM1029-02-ND, Voltage_V=550
J5 J20 J48: library part CMP-0075484-1, "Header, 100mil, 3x1, Gold, TH", Manufacturer=Samtec, Supplier Part Number 1=HTSW-103-07-G-S-ND
J8 J60: "Header, 50mil, 5x2, Gold, TH", Manufacturer="Sullins Connector Solutions", Supplier Part Number 1=S9015E-05-ND
J18: "RJ-45, No LED, tab up, R/A, TH", Color=Black, Manufacturer="TE Connectivity", Supplier Part Number 1=A97716-ND
J19: "Receptacle, USB 2.0, Micro-USB Type B, R/A, SMT", Color=Black, Current_A=1.8, Manufacturer=FCI, Supplier Part Number 1=609-4618-1-ND, Voltage_V=100
J44: library part CMP-0075404-1, "Header, 100mil, 2x2, Gold, TH", Color=Black, Current_A=6.3A, Manufacturer=Samtec, Supplier Part Number 1=SAM1028-02-ND, Voltage_V=550V
J45: library part CMP-0054591-2, "Header, 2.54mm, 10x2, Gold, TH", Color=Black, Manufacturer="Sullins Connector Solutions", Supplier Part Number 1=S2011EC-10-ND
J47 J50: library part CMP-0054990-1, "SMA Straight PCB Socket Die Cast, 50 Ohm, TH", Manufacturer="TE Connectivity", Supplier Part Number 1=A97594-ND
J49 J51 J52 J53: library part CMP-0075483-1, "Header, 100mil, 2x1, Gold, TH", Manufacturer=Samtec, Supplier Part Number 1=SAM8736-ND
L1: "Inductor, Drum Core, Ferrite, 3.3 µH, 1.6 A, 0.14 ohm, SMD", Manufacturer=Coilcraft, Value1="0.14 ohm", Value2=1.6A, ValueDisplayed=3.3µH
L2 L4: library part CMP-0003353-2, "Ferrite Bead, 220 ohm @ 100 MHz, 2.5 A, 0603", Manufacturer=MuRata, PartNumber=BLM18SG221TN1D, Supplier Part Number 1=490-5225-1-ND, Value1="0.04 ohm", Value2=2.5A, ValueDisplayed="220 ohm"
L3: library part CMP-0084018-1, "Coupled inductor, 0.056 ohm, SMD", Manufacturer=MuRata, PartNumber=DLW5BTM102TQ2
L5: library part CMP-0058729-1, "Inductor, Wirewound, Ferrite, 4.7 uH, 3.5 A, 0.0312 ohm, SMD", Manufacturer=MuRata, Value1="0.0312 ohm", Value2=3.5A, ValueDisplayed=4.7uH
L6: library part CMP-0080680-2, "Inductor, Shielded, Ferrite, 150 µH, 0.95 A, 0.379 ohm, SMD", Manufacturer=Coilcraft, Value1="0.379 ohm", Value2=0.95A, ValueDisplayed=150µH
L7: library part CMP-0058569-1, "Inductor, Shielded, Ferrite, 10 uH, 2.9 A, 0.0564 ohm, SMD", Manufacturer=MuRata, PartNumber=1255AY-100M{}P3, Supplier Part Number 1=490-10800-1-ND, Value1="0.0564 ohm", Value2=2.9A, ValueDisplayed=10uH
L8: library part CMP-0076756-1, "Inductor, Shielded, Composite, 4.7 µH, 2.5 A, 0.022 ohm, AEC-Q200 Grade 1, SMD", Manufacturer=Coilcraft, Value1="0.022 ohm", Value2=2.5A, ValueDisplayed=4.7µH
L9: library part CMP-0060942-1, "Inductor, Shielded, Ferrite, 15 uH, 4 A, 0.048 ohm, AEC-Q200 Grade 1, SMD", Manufacturer=Coilcraft, PartNumber=SRT8045-153MEB, Value1="0.048 ohm", Value2=4A, ValueDisplayed=15uH
L10: library part CMP-0076756-1, "Inductor, Shielded, Composite, 2.2 µH, 3.5 A, 0.012 ohm, AEC-Q200 Grade 1, SMD", Manufacturer=Coilcraft, PartNumber=XFL5030-222, Value1="0.012 ohm", Value2=3.5A, ValueDisplayed=2.2µH
L11 L13: library part CMP-0013189-2, "Coupled inductor, 200 uH,  A, 4.5 ohm, SMD", Manufacturer=TDK, Supplier Part Number 1=445-173070-1-ND, ValueDisplayed=200uH
L12 L15: library part CMP-0003355-2, "Ferrite Bead, 330 ohm @ 100 MHz, 1.5 A, 0603", Manufacturer=MuRata, PartNumber=BLM18SG331TN1D, Supplier Part Number 1=490-3997-1-ND, Value1="0.07 ohm", Value2=1.5A, ValueDisplayed="330 ohm"
L14: library part CMP-0084019-1, "Coupled inductor, 0.105 ohm, SMD", Manufacturer=MuRata
L16 L17: library part CMP-0003343-2, "Ferrite Bead, 1000 ohm @ 100 MHz, 0.4 A, 0603", Manufacturer=MuRata, Supplier Part Number 1=490-1015-1-ND, Value1="0.5 ohm", Value2=0.4A, ValueDisplayed="1000 ohm"
L18 L23: library part CMP-0061088-1, "Inductor, Shielded, Composite, 2.2 uH, 6.1 A, 0.0201 ohm, AEC-Q200 Grade 1, SMD", Manufacturer=Coilcraft, Value1="0.0201 ohm", Value2=6.1A, ValueDisplayed=2.2uH
L19: library part CMP-0060942-1, "Inductor, Shielded, Ferrite, 10 uH, 4.2 A, 0.037 ohm, AEC-Q200 Grade 1, SMD", Manufacturer=Coilcraft, Value1="0.037 ohm", Value2=4.2A, ValueDisplayed=10uH
L20: library part CMP-0084005-1, "Inductor, Shielded, Ferrite, 15 µH, 3.5 A, 0.0528 ohm, SMD", Manufacturer=MuRata, PartNumber=1217AS-H-150M{}P3, Value1="0.0528 ohm", Value2=3.5A, ValueDisplayed=15µH
L21 L22: library part CMP-0061084-1, "Inductor, Shielded, Composite, 1 uH, 9 A, 0.0089 ohm, AEC-Q200 Grade 1, SMD", Manufacturer=Coilcraft, Value1="0.0089 ohm", Value2=9A, ValueDisplayed=1uH
Logo2: library part Pb-Free
Logo3: library part FCC_disclaimer, "FCC_disclaimer"
MCU_LEDs: library part CMP-0002934-2, "LED, Rg, SMD", Color=RG, Manufacturer=Avago, Supplier Part Number 1=516-1419-1-ND, Value1=W, Value2=2.2V
Q1: "MOSFET, N-CH, 60 V, 115 A, SOT-23", Alternate Manufacturer=None, Manufacturer="Fairchild Semiconductor", Supplier Part Number 1=2N7002NCT-ND, Value1="? ohm", Value2="? nC"
R1: "RES, 39k ohm, 5%, 0.125W, 0805", Manufacturer=Vishay-Dale, Power_W=0.125, Supplier Part Number 1=71-CRCW0805J-39K-E3, TempCo="200 ppm/C", Tolerance_%=5, Value1=5%, Value2=0.125W, Value_Code=39k0
R2: "RES, 24, 5%, 0.25 W, 1206", Manufacturer=Vishay-Dale, Power_W=0.25, Supplier Part Number 1=541-24ECT-ND, TempCo="200 ppm/C", Tolerance_%=5, Value1=5%, Value2=0.25W, Value_Code=24R0, ValueDisplayed=24
R3: "RES, 10.0, 1%, 0.125 W, 0805", Manufacturer="Yageo America", Power_W=0.125, Supplier Part Number 1=311-10.0CRCT-ND, TempCo="200 ppm/C", Tolerance_%=1, Value1=1%, Value2=0.125W, Value_Code=10R0, ValueDisplayed=10.0
R4: "RES, 8.06 k, 1%, 0.1 W, 0603", Manufacturer=Vishay-Dale, Power_W=0.1, Supplier Part Number 1=541-8.06KHCT-ND, TempCo="100 ppm/C", Tolerance_%=1, Value1=1%, Value2=0.1W, Value_Code=8k06, ValueDisplayed=8.06k
R5: "RES, 4.02 k, 1%, 0.1 W, 0603", Manufacturer=Vishay-Dale, Power_W=0.1, Supplier Part Number 1=541-4.02KHCT-ND, TempCo="100 ppm/C", Tolerance_%=1, Value1=1%, Value2=0.1W, Value_Code=4k02, ValueDisplayed=4.02k
R6: "RES, 100, 5%, 1 W, AEC-Q200 Grade 0, 2512", Manufacturer=Vishay-Dale, Power_W=1, Supplier Part Number 1=541-100XCT-ND, TempCo="200 ppm/C", Tolerance_%=5, Value1=5%, Value2=1W, Value_Code=100R, ValueDisplayed=100
R7: "RES, 11.5 k, 1%, 0.1 W, 0603", Manufacturer=Vishay-Dale, Power_W=0.1, Supplier Part Number 1=541-11.5KHCT-ND, TempCo="100 ppm/C", Tolerance_%=1, Value1=1%, Value2=0.1W, Value_Code=11k5, ValueDisplayed=11.5k
R8: "RES, 0, 5%, 0.125 W, 0603", Manufacturer=Vishay/Beyschlag, Power_W=0.125, Supplier Part Number 1=MCT0603-0.0-ZZCT-ND, TempCo=ppm/C, Tolerance_%=5, Value1=5%, Value2=0.125W, Value_Code=0000, ValueDisplayed=0
R9 R20: "RES, 10.0 k, 1%, 0.1 W, 0603", Manufacturer=Vishay-Dale, Power_W=0.1, Supplier Part Number 1=541-10.0KHCT-ND, TempCo="100 ppm/C", Tolerance_%=1, Value1=1%, Value2=0.1W, Value_Code=10k0, ValueDisplayed=10.0k
R10 R11: "RES, 0.91, 1%, 0.25 W, 0805", Manufacturer=Bourns, Power_W=0.25, TempCo="100 ppm/C", Tolerance_%=1, Value1=1%, Value2=0.25W, Value_Code=R910, ValueDisplayed=0.91
R12 R15: "RES, 24.9 k, 1%, 0.063 W, 0402", Manufacturer=Vishay-Dale, Power_W=0.063, Supplier Part Number 1=541-24.9KLCT-ND, TempCo="100 ppm/C", Tolerance_%=1, Value1=1%, Value2=0.063W, Value_Code=24k9, ValueDisplayed=24.9k
R13: "RES, 1.00 k, 1%, 0.1 W, 0402", Manufacturer=Panasonic, Power_W=0.1, Supplier Part Number 1=P1.00KLCT-ND, TempCo="100 ppm/C", Tolerance_%=1, Value1=1%, Value2=0.1W, Value_Code=1k00, ValueDisplayed=1.00k
R14: "RES, 49.9, 1%, 0.063 W, AEC-Q200 Grade 0, 0402", Manufacturer="Stackpole Electronics Inc", Power_W=0.063, Supplier Part Number 1=RMCF0402FT49R9CT-ND, TempCo="100 ppm/C", Tolerance_%=1, Value1=1%, Value2=0.063W, Value_Code=49R9, ValueDisplayed=49.9
R16: "RES, 47 k, 5%, 0.063 W, 0402", Manufacturer=Vishay-Dale, Power_W=0.063, Supplier Part Number 1=541-47KJCT-ND, TempCo="200 ppm/C", Tolerance_%=5, Value1=5%, Value2=0.063W, Value_Code=47k0, ValueDisplayed=47k
R17: "RES, 649, 1%, 0.1 W, 0603", Manufacturer=Vishay-Dale, Power_W=0.1, Supplier Part Number 1=541-649HCT-ND, TempCo="100 ppm/C", Tolerance_%=1, Value1=1%, Value2=0.1W, Value_Code=649R, ValueDisplayed=649
R18: "RES, 8.66 k, 1%, 0.063 W, 0402", Manufacturer=Vishay-Dale, Power_W=0.063, Supplier Part Number 1=541-8.66KLCT-ND, TempCo="100 ppm/C", Tolerance_%=1, Value1=1%, Value2=0.063W, Value_Code=8k66, ValueDisplayed=8.66k
R19: "RES, 0, 5%, 0.063 W, 0402", Manufacturer="Yageo America", Power_W=0.063, Supplier Part Number 1=311-0.0JRCT-ND, TempCo="200 ppm/C", Tolerance_%=5, Value1=5%, Value2=0.063W, Value_Code=0000, ValueDisplayed=0
R21: "RES, 6.49 k, 1%, 0.063 W, 0402", Manufacturer=Vishay-Dale, Power_W=0.063, Supplier Part Number 1=541-6.49KLCT-ND, TempCo="100 ppm/C", Tolerance_%=1, Value1=1%, Value2=0.063W, Value_Code=6k49, ValueDisplayed=6.49k
R22: "3314 - 4 mm Square Trimpot Trimming Potentiometer", Manufacturer=Bourns, Supplier Part Number 1=3314J-101ECT-ND
R23 R26: "RES, 10, 5%, 0.063 W, 0402", Manufacturer=Vishay-Dale, Power_W=0.063, Supplier Part Number 1=541-10JCT-ND, TempCo="200 ppm/C", Tolerance_%=5, Value1=5%, Value2=0.063W, Value_Code=10R0, ValueDisplayed=10
R24: "RES, 237 k, 1%, 0.063 W, 0402", Manufacturer=Vishay-Dale, Power_W=0.063, Supplier Part Number 1=541-237KLCT-ND, TempCo="100 ppm/C", Tolerance_%=1, Value1=1%, Value2=0.063W, Value_Code=237k
R25: "3314 - 4 mm Square Trimpot Trimming Potentiometer", Manufacturer=Bourns, Supplier Part Number 1=3314J-1-200ECT-ND
R27: "RES, 2.0 k, 5%, 0.1 W, 0603", Manufacturer=Vishay-Dale, Power_W=0.1, Supplier Part Number 1=541-2.0KGCT-ND, TempCo="200 ppm/C", Tolerance_%=5, Value1=5%, Value2=0.1W, Value_Code=2k00, ValueDisplayed=2.0k
R28: "RES, 60.4 k, 1%, 0.063 W, 0402", Manufacturer=Vishay-Dale, Power_W=0.063, Supplier Part Number 1=541-60.4KLCT-ND, TempCo="100 ppm/C", Tolerance_%=1, Value1=1%, Value2=0.063W, Value_Code=60k4, ValueDisplayed=60.4k
R29: "RES, 100 k, 1%, 0.1 W, 0603", Manufacturer="Yageo America", Power_W=0.1, Supplier Part Number 1=311-100KHRCT-ND, TempCo="200 ppm/C", Tolerance_%=1, Value1=1%, Value2=0.1W, Value_Code=100k
R30: "RES, 4.42 k, 1%, 0.063 W, 0402", Manufacturer=Vishay-Dale, Power_W=0.063, Supplier Part Number 1=541-4.42KLCT-ND, TempCo="100 ppm/C", Tolerance_%=1, Value1=1%, Value2=0.063W, Value_Code=4k42, ValueDisplayed=4.42k
R31 R49 R52 R111 R112 R116 R117 R118: "RES, 0, 5%, 0.063 W, 0402", Manufacturer=Vishay-Dale, Power_W=0.063, Supplier Part Number 1=541-0.0JCT-ND, TempCo="200 ppm/C", Tolerance_%=5, Value1=5%, Value2=0.063W, Value_Code=0000, ValueDisplayed=0
R32 R37 R38 R40 R42: "RES, 10.0 k, 1%, 0.063 W, 0402", Manufacturer=Vishay-Dale, Power_W=0.063, Supplier Part Number 1=541-10.0KLCT-ND, TempCo="100 ppm/C", Tolerance_%=1, Value1=1%, Value2=0.063W, Value_Code=10k0, ValueDisplayed=10.0k
R33 R119: "RES, 910, 5%, 0.063 W, 0402", Manufacturer=Vishay-Dale, Power_W=0.063, Supplier Part Number 1=541-910JCT-ND, TempCo="200 ppm/C", Tolerance_%=5, Value1=5%, Value2=0.063W, Value_Code=910R, ValueDisplayed=910
R34: "RES, 7.87, 1%, 0.25 W, 1206", Manufacturer=Vishay-Dale, Power_W=0.25, Supplier Part Number 1=541-7.87FFCT-ND, TempCo="100 ppm/C", Tolerance_%=1, Value1=1%, Value2=0.25W, Value_Code=7R87, ValueDisplayed=7.87
R35: "RES, 7.68 k, 1%, 0.063 W, 0402", Manufacturer=Vishay-Dale, Power_W=0.063, Supplier Part Number 1=541-7.68KLCT-ND, TempCo="100 ppm/C", Tolerance_%=1, Value1=1%, Value2=0.063W, Value_Code=7k68, ValueDisplayed=7.68k
R36: "RES, 56.2 k, 1%, 0.063 W, 0402", Manufacturer=Vishay-Dale, Power_W=0.063, Supplier Part Number 1=541-56.2KLCT-ND, TempCo="100 ppm/C", Tolerance_%=1, Value1=1%, Value2=0.063W, Value_Code=56k2, ValueDisplayed=56.2k
R39: "RES, 33.2 k, 1%, 0.063 W, 0402", Manufacturer=Vishay-Dale, Power_W=0.063, Supplier Part Number 1=541-33.2KLCT-ND, TempCo="100 ppm/C", Tolerance_%=1, Value1=1%, Value2=0.063W, Value_Code=33k2, ValueDisplayed=33.2k
R41: "RES, 13.3 k, 1%, 0.063 W, 0402", Manufacturer=Vishay-Dale, Power_W=0.063, Supplier Part Number 1=541-13.3KLCT-ND, TempCo="100 ppm/C", Tolerance_%=1, Value1=1%, Value2=0.063W, Value_Code=13k3, ValueDisplayed=13.3k
R43 R128: "RES, 68.1 k, 1%, 0.063 W, 0402", Manufacturer=Vishay-Dale, Power_W=0.063, Supplier Part Number 1=541-68.1KLCT-ND, TempCo="100 ppm/C", Tolerance_%=1, Value1=1%, Value2=0.063W, Value_Code=68k1, ValueDisplayed=68.1k
R44: "RES, 27.4 k, 1%, 0.063 W, 0402", Manufacturer=Vishay-Dale, Power_W=0.063, Supplier Part Number 1=541-27.4KLCT-ND, TempCo="100 ppm/C", Tolerance_%=1, Value1=1%, Value2=0.063W, Value_Code=27k4, ValueDisplayed=27.4k
R45 R46 R47 R48: "RES, 75.0 ohm, 1%, 0.1W, 0603", Manufacturer=Vishay-Dale, Power_W=0.1, Supplier Part Number 1=541-75.0HCT-ND, TempCo="100 ppm/C", Tolerance_%=1, Value1=1%, Value2=0.1W, Value_Code=75R0
R50: library part CMP-0026768-2, "RES, 100 k, 0.5%, 0.063 W, AEC-Q200 Grade 0, 0402", Manufacturer=Vishay-Dale, Power_W=63mW, Supplier Part Number 1=541-100KAVCT-ND, TempCo="50 ppm/C", Tolerance_%=0.5%, Value2=0.063W, Value_Code=100k
R51 R95 R97 R99 R122: library part CMP-0026934-3, "RES, 470, 5%, 0.063 W, AEC-Q200 Grade 0, 0402", Manufacturer=Vishay-Dale, Power_W=63mW, Supplier Part Number 1=541-470JCT-ND, TempCo="200 ppm/C", Tolerance_%=5%, Value2=0.063W, Value_Code=470R, ValueDisplayed=470
R53: library part CMP-0026036-3, "RES, 165 k, 1%, 0.063 W, AEC-Q200 Grade 0, 0402", Manufacturer=Vishay-Dale, Power_W=63mW, Supplier Part Number 1=541-165KLCT-ND, TempCo="100 ppm/C", Tolerance_%=1%, Value2=0.063W, Value_Code=165k
R54: library part CMP-0026908-3, "RES, 33, 5%, 0.063 W, AEC-Q200 Grade 0, 0402", Manufacturer=Vishay-Dale, Power_W=63mW, Supplier Part Number 1=541-33JCT-ND, TempCo="200 ppm/C", Tolerance_%=5%, Value2=0.063W, Value_Code=33R0, ValueDisplayed=33
R55: "RES, 510 k, 5%, 0.063 W, 0402", Manufacturer=Vishay-Dale, Power_W=0.063, Supplier Part Number 1=541-510KJCT-ND, TempCo="200 ppm/C", Tolerance_%=5, Value1=5%, Value2=0.063W, Value_Code=510k
R56: "RES, 442 k, 1%, 0.063 W, 0402", Manufacturer=Vishay-Dale, Power_W=0.063, Supplier Part Number 1=541-442KLCT-ND, TempCo="100 ppm/C", Tolerance_%=1, Value1=1%, Value2=0.063W, Value_Code=442k
R57 R60 R63: "RES, 100 k, 0.5%, 0.063 W, 0402", Manufacturer=Vishay-Dale, Power_W=0.063, Supplier Part Number 1=541-100KAVCT-ND, TempCo="50 ppm/C", Tolerance_%=0.5, Value1=0.5%, Value2=0.063W, Value_Code=100k
R58 R65: "RES, 97.6 k, 1%, 0.063 W, 0402", Manufacturer=Vishay-Dale, Power_W=0.063, Supplier Part Number 1=541-97.6KLCT-ND, TempCo="100 ppm/C", Tolerance_%=1, Value1=1%, Value2=0.063W, Value_Code=97k6, ValueDisplayed=97.6k
R59: "RES, 13.7 k, 1%, 0.063 W, 0402", Manufacturer=Vishay-Dale, Power_W=0.063, Supplier Part Number 1=541-13.7KLCT-ND, TempCo="100 ppm/C", Tolerance_%=1, Value1=1%, Value2=0.063W, Value_Code=13k7, ValueDisplayed=13.7k
R61: "RES, 120 k, 1%, 0.063 W, 0402", Manufacturer=Vishay-Dale, Power_W=0.063, Supplier Part Number 1=541-120KLCT-ND, TempCo="100 ppm/C", Tolerance_%=1, Value1=1%, Value2=0.063W, Value_Code=120k
R62: "RES, 124 k, 1%, 0.063 W, 0402", Manufacturer=Vishay-Dale, Power_W=0.063, Supplier Part Number 1=541-124KLCT-ND, TempCo="100 ppm/C", Tolerance_%=1, Value1=1%, Value2=0.063W, Value_Code=124k
R64: "RES, 196 k, 1%, 0.063 W, 0402", Manufacturer=Vishay-Dale, Power_W=0.063, Supplier Part Number 1=541-196KLCT-ND, TempCo="100 ppm/C", Tolerance_%=1, Value1=1%, Value2=0.063W, Value_Code=196k
R66 R67 R68 R113 R114 R115: "RES, 100 k, 5%, 0.063 W, 0402", Manufacturer=Vishay-Dale, Power_W=0.063, Supplier Part Number 1=541-100KJCT-ND, TempCo="200 ppm/C", Tolerance_%=5, Value1=5%, Value2=0.063W, Value_Code=100k
R69 R70: library part CMP-0027127-1, "RES, 470, 5%, 0.05 W, 0201", Manufacturer="Yageo America", Power_W=50mW, Supplier Part Number 1=311-470NCT-ND, TempCo="200 ppm/C", Tolerance_%=5%, Value2=0.05W, Value_Code=470R, ValueDisplayed=470
R71 R72 R100 R105 R108 R124: library part CMP-0027011-4, "RES, 0, 5%, 0.05 W, AEC-Q200 Grade 1, 0201", Manufacturer=Panasonic, Power_W=50mW, Supplier Part Number 1=P0.0AGCT-ND, TempCo="600 ppm/C", Tolerance_%=5%, Value2=0.05W, Value_Code=0000, ValueDisplayed=0
R73 R77 R80 R81 R82 R83 R84 R85 R86 R87 R88 R89 R90 R94: library part CMP-0026822-3, "RES, 0, 5%, 0.063 W, AEC-Q200 Grade 0, 0402", Manufacturer=Vishay-Dale, Power_W=63mW, Supplier Part Number 1=541-0.0JCT-ND, TempCo="200 ppm/C", Tolerance_%=5%, Value2=0.063W, Value_Code=0000, ValueDisplayed=0
R74: library part CMP-0026935-3, "RES, 47 k, 5%, 0.063 W, AEC-Q200 Grade 0, 0402", Manufacturer=Vishay-Dale, Power_W=63mW, Supplier Part Number 1=541-47KJCT-ND, TempCo="200 ppm/C", Tolerance_%=5%, Value2=0.063W, Value_Code=47k0, ValueDisplayed=47k
R75: library part CMP-0026085-3, "RES, 1.40 k, 1%, 0.063 W, AEC-Q200 Grade 0, 0402", Manufacturer=Vishay-Dale, Power_W=63mW, Supplier Part Number 1=541-1.40KLCT-ND, TempCo="100 ppm/C", Tolerance_%=1%, Value2=0.063W, Value_Code=1k40, ValueDisplayed=1.40k
R76: library part CMP-0026100-2, "RES, 1.00 M, 1%, 0.063 W, AEC-Q200 Grade 0, 0402", Manufacturer=Vishay-Dale, Power_W=63mW, Supplier Part Number 1=541-1.00MLCT-ND, TempCo="100 ppm/C", Tolerance_%=1%, Value2=0.063W, Value_Code=1M00, ValueDisplayed=1.00M
R78 R79: library part CMP-0026888-3, "RES, 27, 5%, 0.063 W, AEC-Q200 Grade 0, 0402", Manufacturer=Vishay-Dale, Power_W=63mW, Supplier Part Number 1=541-27JCT-ND, TempCo="200 ppm/C", Tolerance_%=5%, Value2=0.063W, Value_Code=27R0, ValueDisplayed=27
R91: library part CMP-0026890-5, "RES, 2.2 k, 5%, 0.063 W, AEC-Q200 Grade 0, 0402", Manufacturer=Vishay-Dale, Power_W=63mW, Supplier Part Number 1=541-2.2KJCT-ND, TempCo="200 ppm/C", Tolerance_%=5%, Value2=0.063W, Value_Code=2k20, ValueDisplayed=2.2k
R92: library part CMP-0026515-2, "RES, 6.49 k, 1%, 0.063 W, AEC-Q200 Grade 0, 0402", Manufacturer=Vishay-Dale, Power_W=63mW, Supplier Part Number 1=541-6.49KLCT-ND, TempCo="100 ppm/C", Tolerance_%=1%, Value2=0.063W, Value_Code=6k49, ValueDisplayed=6.49k
R93: library part CMP-0027010-2, "RES, 2.2 k, 5%, 0.05 W, 0201", Manufacturer=Vishay-Dale, Power_W=50mW, Supplier Part Number 1=541-2.2KAGCT-ND, TempCo="200 ppm/C", Tolerance_%=5%, Value2=0.05W, Value_Code=2k20, ValueDisplayed=2.2k
R96 R98 R103 R106 R107 R109 R110 R123: library part CMP-0026237-2, "RES, 2.49 k, 1%, 0.063 W, AEC-Q200 Grade 0, 0402", Manufacturer=Vishay-Dale, Power_W=63mW, Supplier Part Number 1=541-2.49KLCT-ND, TempCo="100 ppm/C", Tolerance_%=1%, Value2=0.063W, Value_Code=2k49, ValueDisplayed=2.49k
R101 R102: library part CMP-0016535-2, "RES, 1.00 M, 1%, 1 W, 2010", Manufacturer="Stackpole Electronics Inc", Power_W=1W, Supplier Part Number 1=HVCB2010FKC1M00CT-ND, TempCo="50 ppm/C", Tolerance_%=1%, Value_Code=1M00, ValueDisplayed=1.00M
R104: library part CMP-0026727-1, "RES, 1.00 M, 1%, 0.063 W, 0402", Manufacturer="Yageo America", Power_W=63mW, Supplier Part Number 1=311-1.00MLRCT-ND, TempCo="100 ppm/C", Tolerance_%=1%, Value2=0.063W, Value_Code=1M00, ValueDisplayed=1.00M
R120: "RES, 0.1, 1%, 0.5 W, 1206", Manufacturer="Stackpole Electronics Inc", Power_W=0.5, Supplier Part Number 1=CSR1206FKR100CT-ND, TempCo="100 ppm/C", Tolerance_%=1, Value1=1%, Value2=0.5W, Value_Code=R100, ValueDisplayed=0.1
R121: "RES, 0.033, 1%, 1 W, AEC-Q200 Grade 0, 1206", Manufacturer=Panasonic, Power_W=1, Supplier Part Number 1=P0.033BVCT-ND, TempCo="50 ppm/C", Value1=1%, Value2=1W, Value_Code=R033, ValueDisplayed=0.033
R125 R130: "RES, 4.99 k, 1%, 0.063 W, 0402", Manufacturer=Vishay-Dale, Power_W=0.063, Supplier Part Number 1=541-4.99KLCT-ND, TempCo="100 ppm/C", Tolerance_%=1, Value1=1%, Value2=0.063W, Value_Code=4k99, ValueDisplayed=4.99k
R126 R131 R132: "RES, 0, 5%, 0.25 W, 1206", Manufacturer=Vishay-Dale, Power_W=0.25, Supplier Part Number 1=541-0.0ECT-ND, TempCo="200 ppm/C", Tolerance_%=5, Value1=5%, Value2=0.25W, Value_Code=0000, ValueDisplayed=0
R127: "RES, 91 k, 5%, 0.1 W, 0603", Manufacturer=Vishay-Dale, Power_W=0.1, Supplier Part Number 1=541-91KGCT-ND, TempCo="200 ppm/C", Tolerance_%=5, Value1=5%, Value2=0.1W, Value_Code=91k0, ValueDisplayed=91k
R129: "RES, 4.87 k, 1%, 0.063 W, 0402", Manufacturer=Vishay-Dale, Power_W=0.063, Supplier Part Number 1=541-4.87KLCT-ND, TempCo="100 ppm/C", Tolerance_%=1, Value1=1%, Value2=0.063W, Value_Code=4k87, ValueDisplayed=4.87k
RESET: library part CMP-0002193-2, "Switch, SPST-NO, Off-Mom, 12 V, SMD", CurrentRating_mA=50A, Manufacturer="Omron Electronic Components", Supplier Part Number 1=SW1021CT-ND
T1: library part LDT0937-50, "Transformer, 150 uH, SMT", Manufacturer="Linkcom Manufacturing Co.", ValueDisplayed=150µH
T2: "Transformer, 350uH, SMT", Manufacturer="Pulse Engineering"
U1: "IEEE 802.3at PoE PD with No-Opto Flyback DC-DC Controller, RJJ0023B (VQFN-23)", Alternate Manufacturer="Texas Instruments"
